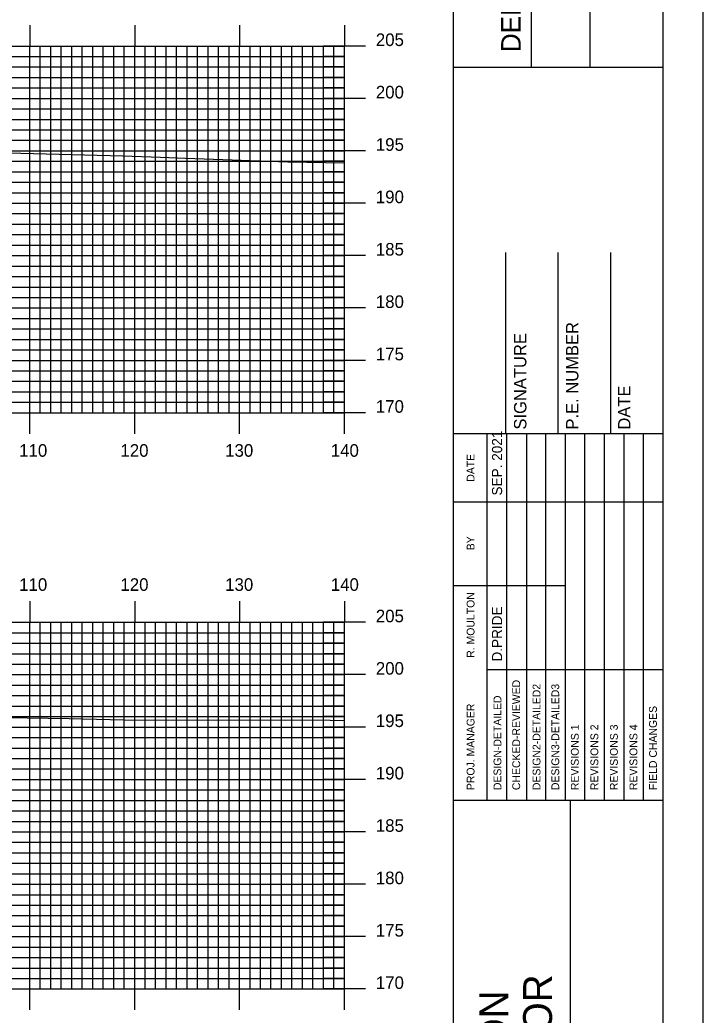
# Model space of a CAD drawing. Extents: x 1796420 to 1796763, y 442591 to 442811.
# Drawn here: x 1796695 to 1796760.1, y 442666.2 to 442761.2 of the extents above; entities that cross this region are included whole.
import ezdxf

# ---------------------------------------------------------------- set-up
doc = ezdxf.new("R2010")
doc.units = 0
for name, color, linetype in [('BORDER', 7, 'Continuous'), ('H_V ANNOTATION', 7, 'Continuous'), ('MAJOR', 7, 'Continuous'), ('MINOR', 7, 'Continuous'), ('PLOT BOUNDARY', 7, 'Continuous'), ('S_Roadway_Centerline', 7, 'Continuous')]:
    doc.layers.add(name, color=color, linetype=linetype)

msp = doc.modelspace()

# ---------------------------------------------------------------- linework, layer by layer
at = {"layer": 'BORDER'}
for p, q in [((1796736.305, 442596.665), (1796736.305, 442806.665)), ((1796743.762, 442756.659), (1796743.762, 442806.659)), ((1796749.352, 442756.659), (1796749.352, 442806.659)), ((1796736.307, 442756.653), (1796756.305, 442756.653)), ((1796741.305, 442721.671), (1796741.305, 442738.966)), ((1796746.305, 442721.671), (1796746.305, 442738.966)), ((1796751.305, 442721.671), (1796751.305, 442738.966)), ((1796736.305, 442721.671), (1796756.305, 442721.671)), ((1796736.305, 442686.671), (1796756.305, 442686.671)), ((1796747.487, 442616.671), (1796747.487, 442686.671))]:
    msp.add_line(p, q, dxfattribs=at)
msp.add_lwpolyline([(1796436.305, 442596.665), (1796756.305, 442596.665), (1796756.305, 442806.665), (1796436.305, 442806.665)], close=True, dxfattribs=at)
for points in [[(1796739.535, 442715.171), (1796739.535, 442721.671)], [(1796741.4, 442686.677), (1796741.4, 442721.671)], [(1796743.264, 442721.671), (1796743.264, 442686.677)], [(1796745.127, 442686.677), (1796745.127, 442721.671)], [(1796746.99, 442686.677), (1796746.99, 442721.671)], [(1796748.854, 442686.677), (1796748.854, 442721.671)], [(1796750.717, 442686.677), (1796750.717, 442721.671)], [(1796752.58, 442686.677), (1796752.58, 442721.671)], [(1796754.444, 442686.677), (1796754.444, 442721.671)], [(1796739.537, 442686.677), (1796739.537, 442720.259)], [(1796736.305, 442715.171), (1796756.305, 442715.171)], [(1796736.305, 442707.171), (1796739.537, 442707.171)], [(1796739.535, 442707.171), (1796746.988, 442707.171)], [(1796739.535, 442699.171), (1796756.305, 442699.171)]]:
    msp.add_lwpolyline(points, dxfattribs=at)
at = {"layer": 'MAJOR'}
for p, q in [((1796695.905, 442760.669), (1796695.905, 442758.665)), ((1796705.905, 442760.669), (1796705.905, 442758.665)), ((1796715.905, 442760.669), (1796715.905, 442758.665)), ((1796725.905, 442760.669), (1796725.905, 442758.665)), ((1796445.905, 442758.665), (1796725.905, 442758.665)), ((1796445.905, 442758.665), (1796725.905, 442758.665)), ((1796695.905, 442723.665), (1796695.905, 442758.665)), ((1796705.905, 442723.665), (1796705.905, 442758.665)), ((1796715.905, 442723.665), (1796715.905, 442758.665)), ((1796727.909, 442758.665), (1796723.901, 442758.665)), ((1796725.905, 442723.665), (1796725.905, 442758.665)), ((1796725.905, 442723.665), (1796725.905, 442758.665)), ((1796445.905, 442753.665), (1796725.905, 442753.665)), ((1796727.909, 442753.665), (1796723.901, 442753.665)), ((1796445.905, 442748.665), (1796725.905, 442748.665)), ((1796727.909, 442748.665), (1796723.901, 442748.665)), ((1796445.905, 442743.665), (1796725.905, 442743.665)), ((1796727.909, 442743.665), (1796723.901, 442743.665)), ((1796445.905, 442738.665), (1796725.905, 442738.665)), ((1796727.909, 442738.665), (1796723.901, 442738.665)), ((1796445.905, 442733.665), (1796725.905, 442733.665)), ((1796727.909, 442733.665), (1796723.901, 442733.665)), ((1796445.905, 442728.665), (1796725.905, 442728.665)), ((1796727.909, 442728.665), (1796723.901, 442728.665)), ((1796445.905, 442723.665), (1796725.905, 442723.665)), ((1796445.905, 442723.665), (1796725.905, 442723.665)), ((1796695.905, 442721.661), (1796695.905, 442723.665)), ((1796705.905, 442721.661), (1796705.905, 442723.665)), ((1796715.905, 442721.661), (1796715.905, 442723.665)), ((1796727.909, 442723.665), (1796723.901, 442723.665)), ((1796725.905, 442721.661), (1796725.905, 442723.665)), ((1796695.905, 442705.669), (1796695.905, 442703.665)), ((1796705.905, 442705.669), (1796705.905, 442703.665)), ((1796715.905, 442705.669), (1796715.905, 442703.665)), ((1796725.905, 442705.669), (1796725.905, 442703.665)), ((1796445.905, 442703.665), (1796725.905, 442703.665)), ((1796445.905, 442703.665), (1796725.905, 442703.665)), ((1796695.905, 442668.665), (1796695.905, 442703.665)), ((1796705.905, 442668.665), (1796705.905, 442703.665)), ((1796715.905, 442668.665), (1796715.905, 442703.665)), ((1796727.909, 442703.665), (1796723.901, 442703.665)), ((1796725.905, 442668.665), (1796725.905, 442703.665)), ((1796725.905, 442668.665), (1796725.905, 442703.665)), ((1796445.905, 442698.665), (1796725.905, 442698.665)), ((1796727.909, 442698.665), (1796723.901, 442698.665)), ((1796445.905, 442693.665), (1796725.905, 442693.665)), ((1796727.909, 442693.665), (1796723.901, 442693.665)), ((1796445.905, 442688.665), (1796725.905, 442688.665)), ((1796727.909, 442688.665), (1796723.901, 442688.665)), ((1796445.905, 442683.665), (1796725.905, 442683.665)), ((1796727.909, 442683.665), (1796723.901, 442683.665)), ((1796445.905, 442678.665), (1796725.905, 442678.665)), ((1796727.909, 442678.665), (1796723.901, 442678.665)), ((1796445.905, 442673.665), (1796725.905, 442673.665)), ((1796727.909, 442673.665), (1796723.901, 442673.665)), ((1796445.905, 442668.665), (1796725.905, 442668.665)), ((1796445.905, 442668.665), (1796725.905, 442668.665)), ((1796695.905, 442666.661), (1796695.905, 442668.665)), ((1796705.905, 442666.661), (1796705.905, 442668.665)), ((1796715.905, 442666.661), (1796715.905, 442668.665)), ((1796727.909, 442668.665), (1796723.901, 442668.665)), ((1796725.905, 442666.661), (1796725.905, 442668.665))]:
    msp.add_line(p, q, dxfattribs=at)
at = {"layer": 'MINOR'}
for p, q in [((1796696.905, 442723.665), (1796696.905, 442758.665)), ((1796697.905, 442723.665), (1796697.905, 442758.665)), ((1796698.905, 442723.665), (1796698.905, 442758.665)), ((1796699.905, 442723.665), (1796699.905, 442758.665)), ((1796700.905, 442723.665), (1796700.905, 442758.665)), ((1796701.905, 442723.665), (1796701.905, 442758.665)), ((1796702.905, 442723.665), (1796702.905, 442758.665)), ((1796703.905, 442723.665), (1796703.905, 442758.665)), ((1796704.905, 442723.665), (1796704.905, 442758.665)), ((1796706.905, 442723.665), (1796706.905, 442758.665)), ((1796707.905, 442723.665), (1796707.905, 442758.665)), ((1796708.905, 442723.665), (1796708.905, 442758.665)), ((1796709.905, 442723.665), (1796709.905, 442758.665)), ((1796710.905, 442723.665), (1796710.905, 442758.665)), ((1796711.905, 442723.665), (1796711.905, 442758.665)), ((1796712.905, 442723.665), (1796712.905, 442758.665)), ((1796713.905, 442723.665), (1796713.905, 442758.665)), ((1796714.905, 442723.665), (1796714.905, 442758.665)), ((1796716.905, 442723.665), (1796716.905, 442758.665)), ((1796717.905, 442723.665), (1796717.905, 442758.665)), ((1796718.905, 442723.665), (1796718.905, 442758.665)), ((1796719.905, 442723.665), (1796719.905, 442758.665)), ((1796720.905, 442723.665), (1796720.905, 442758.665)), ((1796721.905, 442723.665), (1796721.905, 442758.665)), ((1796722.905, 442723.665), (1796722.905, 442758.665)), ((1796723.905, 442723.665), (1796723.905, 442758.665)), ((1796724.905, 442723.665), (1796724.905, 442758.665)), ((1796445.905, 442757.665), (1796725.905, 442757.665)), ((1796725.905, 442757.665), (1796723.901, 442757.665)), ((1796445.905, 442756.665), (1796725.905, 442756.665)), ((1796725.905, 442756.665), (1796723.901, 442756.665)), ((1796445.905, 442755.665), (1796725.905, 442755.665)), ((1796725.905, 442755.665), (1796723.901, 442755.665)), ((1796445.905, 442754.665), (1796725.905, 442754.665)), ((1796725.905, 442754.665), (1796723.901, 442754.665)), ((1796445.905, 442752.665), (1796725.905, 442752.665)), ((1796725.905, 442752.665), (1796723.901, 442752.665)), ((1796445.905, 442751.665), (1796725.905, 442751.665)), ((1796725.905, 442751.665), (1796723.901, 442751.665)), ((1796445.905, 442750.665), (1796725.905, 442750.665)), ((1796725.905, 442750.665), (1796723.901, 442750.665)), ((1796445.905, 442749.665), (1796725.905, 442749.665)), ((1796725.905, 442749.665), (1796723.901, 442749.665)), ((1796445.905, 442747.665), (1796725.905, 442747.665)), ((1796725.905, 442747.665), (1796723.901, 442747.665)), ((1796445.905, 442746.665), (1796725.905, 442746.665)), ((1796725.905, 442746.665), (1796723.901, 442746.665)), ((1796445.905, 442745.665), (1796725.905, 442745.665)), ((1796725.905, 442745.665), (1796723.901, 442745.665)), ((1796445.905, 442744.665), (1796725.905, 442744.665)), ((1796725.905, 442744.665), (1796723.901, 442744.665)), ((1796445.905, 442742.665), (1796725.905, 442742.665)), ((1796725.905, 442742.665), (1796723.901, 442742.665)), ((1796445.905, 442741.665), (1796725.905, 442741.665)), ((1796725.905, 442741.665), (1796723.901, 442741.665)), ((1796445.905, 442740.665), (1796725.905, 442740.665)), ((1796725.905, 442740.665), (1796723.901, 442740.665)), ((1796445.905, 442739.665), (1796725.905, 442739.665)), ((1796725.905, 442739.665), (1796723.901, 442739.665)), ((1796445.905, 442737.665), (1796725.905, 442737.665)), ((1796725.905, 442737.665), (1796723.901, 442737.665)), ((1796445.905, 442736.665), (1796725.905, 442736.665)), ((1796725.905, 442736.665), (1796723.901, 442736.665)), ((1796445.905, 442735.665), (1796725.905, 442735.665)), ((1796725.905, 442735.665), (1796723.901, 442735.665)), ((1796445.905, 442734.665), (1796725.905, 442734.665)), ((1796725.905, 442734.665), (1796723.901, 442734.665)), ((1796445.905, 442732.665), (1796725.905, 442732.665)), ((1796725.905, 442732.665), (1796723.901, 442732.665)), ((1796445.905, 442731.665), (1796725.905, 442731.665)), ((1796725.905, 442731.665), (1796723.901, 442731.665)), ((1796445.905, 442730.665), (1796725.905, 442730.665)), ((1796725.905, 442730.665), (1796723.901, 442730.665)), ((1796445.905, 442729.665), (1796725.905, 442729.665)), ((1796725.905, 442729.665), (1796723.901, 442729.665)), ((1796445.905, 442727.665), (1796725.905, 442727.665)), ((1796725.905, 442727.665), (1796723.901, 442727.665)), ((1796445.905, 442726.665), (1796725.905, 442726.665)), ((1796725.905, 442726.665), (1796723.901, 442726.665)), ((1796445.905, 442725.665), (1796725.905, 442725.665)), ((1796725.905, 442725.665), (1796723.901, 442725.665)), ((1796445.905, 442724.665), (1796725.905, 442724.665)), ((1796725.905, 442724.665), (1796723.901, 442724.665)), ((1796696.905, 442668.665), (1796696.905, 442703.665)), ((1796697.905, 442668.665), (1796697.905, 442703.665)), ((1796698.905, 442668.665), (1796698.905, 442703.665)), ((1796699.905, 442668.665), (1796699.905, 442703.665)), ((1796700.905, 442668.665), (1796700.905, 442703.665)), ((1796701.905, 442668.665), (1796701.905, 442703.665)), ((1796702.905, 442668.665), (1796702.905, 442703.665)), ((1796703.905, 442668.665), (1796703.905, 442703.665)), ((1796704.905, 442668.665), (1796704.905, 442703.665)), ((1796706.905, 442668.665), (1796706.905, 442703.665)), ((1796707.905, 442668.665), (1796707.905, 442703.665)), ((1796708.905, 442668.665), (1796708.905, 442703.665)), ((1796709.905, 442668.665), (1796709.905, 442703.665)), ((1796710.905, 442668.665), (1796710.905, 442703.665)), ((1796711.905, 442668.665), (1796711.905, 442703.665)), ((1796712.905, 442668.665), (1796712.905, 442703.665)), ((1796713.905, 442668.665), (1796713.905, 442703.665)), ((1796714.905, 442668.665), (1796714.905, 442703.665)), ((1796716.905, 442668.665), (1796716.905, 442703.665)), ((1796717.905, 442668.665), (1796717.905, 442703.665)), ((1796718.905, 442668.665), (1796718.905, 442703.665)), ((1796719.905, 442668.665), (1796719.905, 442703.665)), ((1796720.905, 442668.665), (1796720.905, 442703.665)), ((1796721.905, 442668.665), (1796721.905, 442703.665)), ((1796722.905, 442668.665), (1796722.905, 442703.665)), ((1796723.905, 442668.665), (1796723.905, 442703.665)), ((1796724.905, 442668.665), (1796724.905, 442703.665)), ((1796445.905, 442702.665), (1796725.905, 442702.665)), ((1796725.905, 442702.665), (1796723.901, 442702.665)), ((1796445.905, 442701.665), (1796725.905, 442701.665)), ((1796725.905, 442701.665), (1796723.901, 442701.665)), ((1796445.905, 442700.665), (1796725.905, 442700.665)), ((1796725.905, 442700.665), (1796723.901, 442700.665)), ((1796445.905, 442699.665), (1796725.905, 442699.665)), ((1796725.905, 442699.665), (1796723.901, 442699.665)), ((1796445.905, 442697.665), (1796725.905, 442697.665)), ((1796725.905, 442697.665), (1796723.901, 442697.665)), ((1796445.905, 442696.665), (1796725.905, 442696.665)), ((1796725.905, 442696.665), (1796723.901, 442696.665)), ((1796445.905, 442695.665), (1796725.905, 442695.665)), ((1796725.905, 442695.665), (1796723.901, 442695.665)), ((1796445.905, 442694.665), (1796725.905, 442694.665)), ((1796725.905, 442694.665), (1796723.901, 442694.665)), ((1796445.905, 442692.665), (1796725.905, 442692.665)), ((1796725.905, 442692.665), (1796723.901, 442692.665)), ((1796445.905, 442691.665), (1796725.905, 442691.665)), ((1796725.905, 442691.665), (1796723.901, 442691.665)), ((1796445.905, 442690.665), (1796725.905, 442690.665)), ((1796725.905, 442690.665), (1796723.901, 442690.665)), ((1796445.905, 442689.665), (1796725.905, 442689.665)), ((1796725.905, 442689.665), (1796723.901, 442689.665)), ((1796445.905, 442687.665), (1796725.905, 442687.665)), ((1796725.905, 442687.665), (1796723.901, 442687.665)), ((1796445.905, 442686.665), (1796725.905, 442686.665)), ((1796725.905, 442686.665), (1796723.901, 442686.665)), ((1796445.905, 442685.665), (1796725.905, 442685.665)), ((1796725.905, 442685.665), (1796723.901, 442685.665)), ((1796445.905, 442684.665), (1796725.905, 442684.665)), ((1796725.905, 442684.665), (1796723.901, 442684.665)), ((1796445.905, 442682.665), (1796725.905, 442682.665)), ((1796725.905, 442682.665), (1796723.901, 442682.665)), ((1796445.905, 442681.665), (1796725.905, 442681.665)), ((1796725.905, 442681.665), (1796723.901, 442681.665)), ((1796445.905, 442680.665), (1796725.905, 442680.665)), ((1796725.905, 442680.665), (1796723.901, 442680.665)), ((1796445.905, 442679.665), (1796725.905, 442679.665)), ((1796725.905, 442679.665), (1796723.901, 442679.665)), ((1796445.905, 442677.665), (1796725.905, 442677.665)), ((1796725.905, 442677.665), (1796723.901, 442677.665)), ((1796445.905, 442676.665), (1796725.905, 442676.665)), ((1796725.905, 442676.665), (1796723.901, 442676.665)), ((1796445.905, 442675.665), (1796725.905, 442675.665)), ((1796725.905, 442675.665), (1796723.901, 442675.665)), ((1796445.905, 442674.665), (1796725.905, 442674.665)), ((1796725.905, 442674.665), (1796723.901, 442674.665)), ((1796445.905, 442672.665), (1796725.905, 442672.665)), ((1796725.905, 442672.665), (1796723.901, 442672.665)), ((1796445.905, 442671.665), (1796725.905, 442671.665)), ((1796725.905, 442671.665), (1796723.901, 442671.665)), ((1796445.905, 442670.665), (1796725.905, 442670.665)), ((1796725.905, 442670.665), (1796723.901, 442670.665)), ((1796445.905, 442669.665), (1796725.905, 442669.665)), ((1796725.905, 442669.665), (1796723.901, 442669.665))]:
    msp.add_line(p, q, dxfattribs=at)
at = {"layer": 'PLOT BOUNDARY'}
msp.add_lwpolyline([(1796420.119, 442590.547), (1796760.119, 442590.547), (1796760.119, 442810.547), (1796420.119, 442810.547)], close=True, dxfattribs=at)
at = {"layer": 'S_Roadway_Centerline'}
for points in [[(1796626.071, 442749.969), (1796631.131, 442749.849), (1796637.82, 442749.683), (1796647.695, 442749.521), (1796649.505, 442749.486), (1796650.731, 442749.461), (1796658.17, 442749.303), (1796671.118, 442748.982), (1796673.023, 442748.918), (1796676.121, 442748.846), (1796684.971, 442748.547), (1796691.365, 442748.521), (1796704.774, 442748.192), (1796708.367, 442748.062), (1796710.756, 442747.974), (1796720.517, 442747.622), (1796725.905, 442747.531)], [(1796628.631, 442695.819), (1796633.062, 442695.871), (1796645.252, 442695.8), (1796662.272, 442695.504), (1796665.317, 442695.495), (1796675.895, 442695.275), (1796685.095, 442694.781), (1796687.609, 442694.728), (1796691.607, 442694.613), (1796699.665, 442694.494), (1796704.871, 442694.35), (1796720.251, 442694.317), (1796722.817, 442694.352), (1796724.551, 442694.313), (1796725.905, 442694.283)]]:
    msp.add_lwpolyline(points, dxfattribs=at)

# ---------------------------------------------------------------- texts
at = {"layer": 'BORDER'}
for s, height, p in [('DEPARTMENT OF TRANSPORTATION', 1.86351, (1796742.719, 442758.077)), ('P.E. NUMBER', 1.1811, (1796748.227, 442722.055)), ('SIGNATURE', 1.1811, (1796743.266, 442722.055)), ('DATE', 1.1811, (1796753.187, 442722.055)), ('SEP. 2021', 0.9691, (1796740.952, 442715.762)), ('DATE', 0.7428, (1796738.314, 442717.083)), ('BY', 0.7428, (1796738.314, 442710.541)), ('R. MOULTON', 0.7455, (1796738.315, 442700.276)), ('D.PRIDE', 0.9691, (1796740.952, 442699.917)), ('CHECKED-REVIEWED', 0.7455, (1796742.667, 442687.647)), ('DESIGN2-DETAILED2', 0.7455, (1796744.605, 442687.647)), ('DESIGN3-DETAILED3', 0.7455, (1796746.394, 442687.647)), ('DESIGN-DETAILED', 0.7455, (1796740.878, 442687.647)), ('PROJ. MANAGER', 0.7455, (1796738.314, 442687.647)), ('FIELD CHANGES', 0.7455, (1796755.711, 442687.647)), ('REVISIONS 1', 0.7455, (1796748.257, 442687.647)), ('REVISIONS 2', 0.7455, (1796750.121, 442687.647)), ('REVISIONS 3', 0.7455, (1796751.984, 442687.647)), ('REVISIONS 4', 0.7455, (1796753.847, 442687.647)), ('1-395/ROUTE 9 CONNECTOR', 2.75575, (1796745.708, 442618.865)), ('BREWER TO EDDINGTON', 2.75575, (1796741.529, 442623.074))]:
    msp.add_text(s, height=height, rotation=90, dxfattribs=at).set_placement(p)
at = {"layer": 'H_V ANNOTATION'}
for s, p in [('205', (1796728.905, 442758.665)), ('200', (1796728.905, 442753.665)), ('195', (1796728.905, 442748.665)), ('190', (1796728.905, 442743.665)), ('185', (1796728.905, 442738.665)), ('180', (1796728.905, 442733.665)), ('175', (1796728.905, 442728.665)), ('170', (1796728.905, 442723.665)), ('110', (1796694.889, 442719.465)), ('120', (1796704.546, 442719.465)), ('130', (1796714.535, 442719.465)), ('140', (1796724.61, 442719.465)), ('110', (1796694.889, 442706.665)), ('120', (1796704.546, 442706.665)), ('130', (1796714.535, 442706.665)), ('140', (1796724.61, 442706.665)), ('205', (1796728.905, 442703.665)), ('200', (1796728.905, 442698.665)), ('195', (1796728.905, 442693.665)), ('190', (1796728.905, 442688.665)), ('185', (1796728.905, 442683.665)), ('180', (1796728.905, 442678.665)), ('175', (1796728.905, 442673.665)), ('170', (1796728.905, 442668.665))]:
    msp.add_text(s, height=1.2, dxfattribs=at).set_placement(p)

doc.saveas('drawing.dxf')
